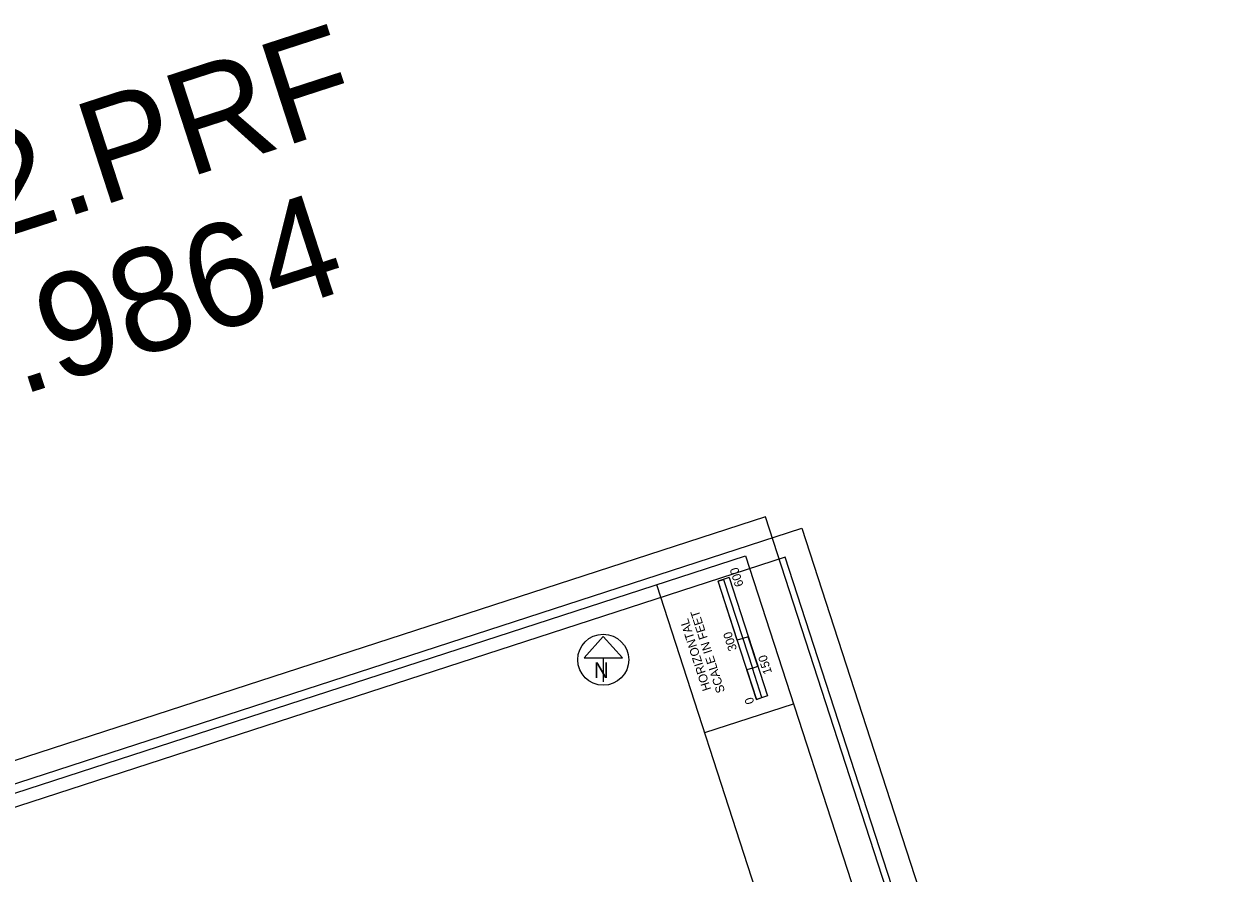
# Model space of a CAD drawing. Extents: x -468556195 to 3353078, y -306091294 to 1252632.
# Drawn here: x 1831176 to 1836968, y 537403 to 541504 of the extents above; entities that cross this region are included whole.
import ezdxf

# ---------------------------------------------------------------- set-up
doc = ezdxf.new("R2010")
doc.units = 0
for name, color, linetype in [('DT_X_Terrain_Ground_Line', 7, 'Continuous'), ('Level 63', 7, 'Continuous'), ('SH_Border', 7, 'Continuous'), ('SH_Cut_Line', 7, 'Continuous'), ('SH_Data', 7, 'Continuous'), ('SH_Masking', 7, 'Continuous'), ('SH_Text', 7, 'Continuous')]:
    doc.layers.add(name, color=color, linetype=linetype)

msp = doc.modelspace()

# ---------------------------------------------------------------- linework, layer by layer
at = {"layer": 'Level 63'}
for points in [[(1825229.4, 535921.9), (1834930.2, 539071.3), (1836968, 532794.6), (1827267.2, 529645.1)], [(1827336.2, 529818.9), (1836809.4, 532894.5), (1834849.2, 538932.3), (1825375.9, 535856.7)]]:
    msp.add_lwpolyline(points, close=True, dxfattribs=at)
at = {"layer": 'SH_Border'}
for p, q in [((1836175.1, 532806.4), (1834229.7, 538798.6)), ((1834461.3, 538085.2), (1834889.3, 538224.2))]:
    msp.add_line(p, q, dxfattribs=at)
msp.add_lwpolyline([(1825526.9, 535973.1), (1834657.8, 538937.5), (1836603.1, 532945.4), (1827472.3, 529981)], close=True, dxfattribs=at)
at = {"layer": 'SH_Cut_Line'}
msp.add_lwpolyline([(1827090.6, 529699.4), (1836792.1, 532849), (1834754.1, 539126.5), (1825052.6, 535976.8)], close=True, dxfattribs=at)
at = {"layer": 'SH_Data'}
for p, q in [((1834579.4, 538833.2), (1834525.9, 538815.8)), ((1834525.9, 538815.8), (1834552.5, 538824.5)), ((1834711.2, 538245.2), (1834525.9, 538815.8)), ((1834618.5, 538530.5), (1834525.9, 538815.8)), ((1834552.5, 538824.5), (1834552.7, 538824.6)), ((1834552.7, 538824.6), (1834645.4, 538539.2)), ((1834579.4, 538833.2), (1834764.7, 538262.5)), ((1834645.4, 538539.2), (1834618.5, 538530.5)), ((1834671.8, 538547.8), (1834645.1, 538539.2)), ((1834645.1, 538539.2), (1834691.5, 538396.5)), ((1834718.1, 538405.1), (1834671.8, 538547.8)), ((1834691.5, 538396.5), (1834664.8, 538387.8)), ((1834691.5, 538396.5), (1834718.1, 538405.1)), ((1834737.8, 538253.8), (1834691.5, 538396.5)), ((1834664.8, 538387.8), (1834711.2, 538245.2)), ((1834764.7, 538262.5), (1834711.2, 538245.2)), ((1834711.2, 538245.2), (1834737.8, 538253.8))]:
    msp.add_line(p, q, dxfattribs=at)
at = {"layer": 'SH_Masking'}
msp.add_circle((1833971.6, 538436.7), 123, dxfattribs=at)
at = {"layer": 'SH_Text'}
for p, q in [((1833971.6, 538548.8), (1833879.4, 538446.4)), ((1834063.9, 538446.5), (1833971.6, 538548.8)), ((1833879.4, 538446.4), (1834063.9, 538446.5)), ((1833971.6, 538446.4), (1833971.6, 538330.4))]:
    msp.add_line(p, q, dxfattribs=at)
msp.add_circle((1833971.6, 538436.7), 123, dxfattribs=at)

# ---------------------------------------------------------------- texts
at = {"layer": 'DT_X_Terrain_Ground_Line'}
for s, p in [('24336GB02.PRF', (1827973.5, 539464.7)), ('24336GB02.PRF', (1827973.5, 539464.7)), ('ROT=17.9864', (1828737.7, 538924.3)), ('ROT=17.9864', (1828737.7, 538924.3))]:
    msp.add_text(s, height=500, rotation=17.98637, dxfattribs=at).set_placement(p)
at = {"layer": 'SH_Data'}
for s, p in [('600', (1834649.9, 538796.8)), ('HORIZONTAL', (1834492.8, 538294.3)), ('SCALE IN FEET', (1834560, 538284.1)), ('300', (1834618.1, 538486.8)), ('150', (1834787, 538374.6)), ('0', (1834701.6, 538229.8))]:
    msp.add_text(s, height=42, rotation=107.9864, dxfattribs=at).set_placement(p)
at = {"layer": 'SH_Text'}
msp.add_text('N', height=75, rotation=0.00095, dxfattribs=at).set_placement((1833926.2, 538349.3))

doc.saveas('drawing.dxf')
